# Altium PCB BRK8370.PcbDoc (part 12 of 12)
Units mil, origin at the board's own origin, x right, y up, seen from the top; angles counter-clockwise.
Board outline 8267.72 x 5708.66 mil, 6 copper layers (L1-TOP, L2-GND, L3-PWR, L4-PWR, L5-GND, L6-BOT), stack 68.606 mil thick; 319 components, 516 nets, 2008 pads, 1743 vias.
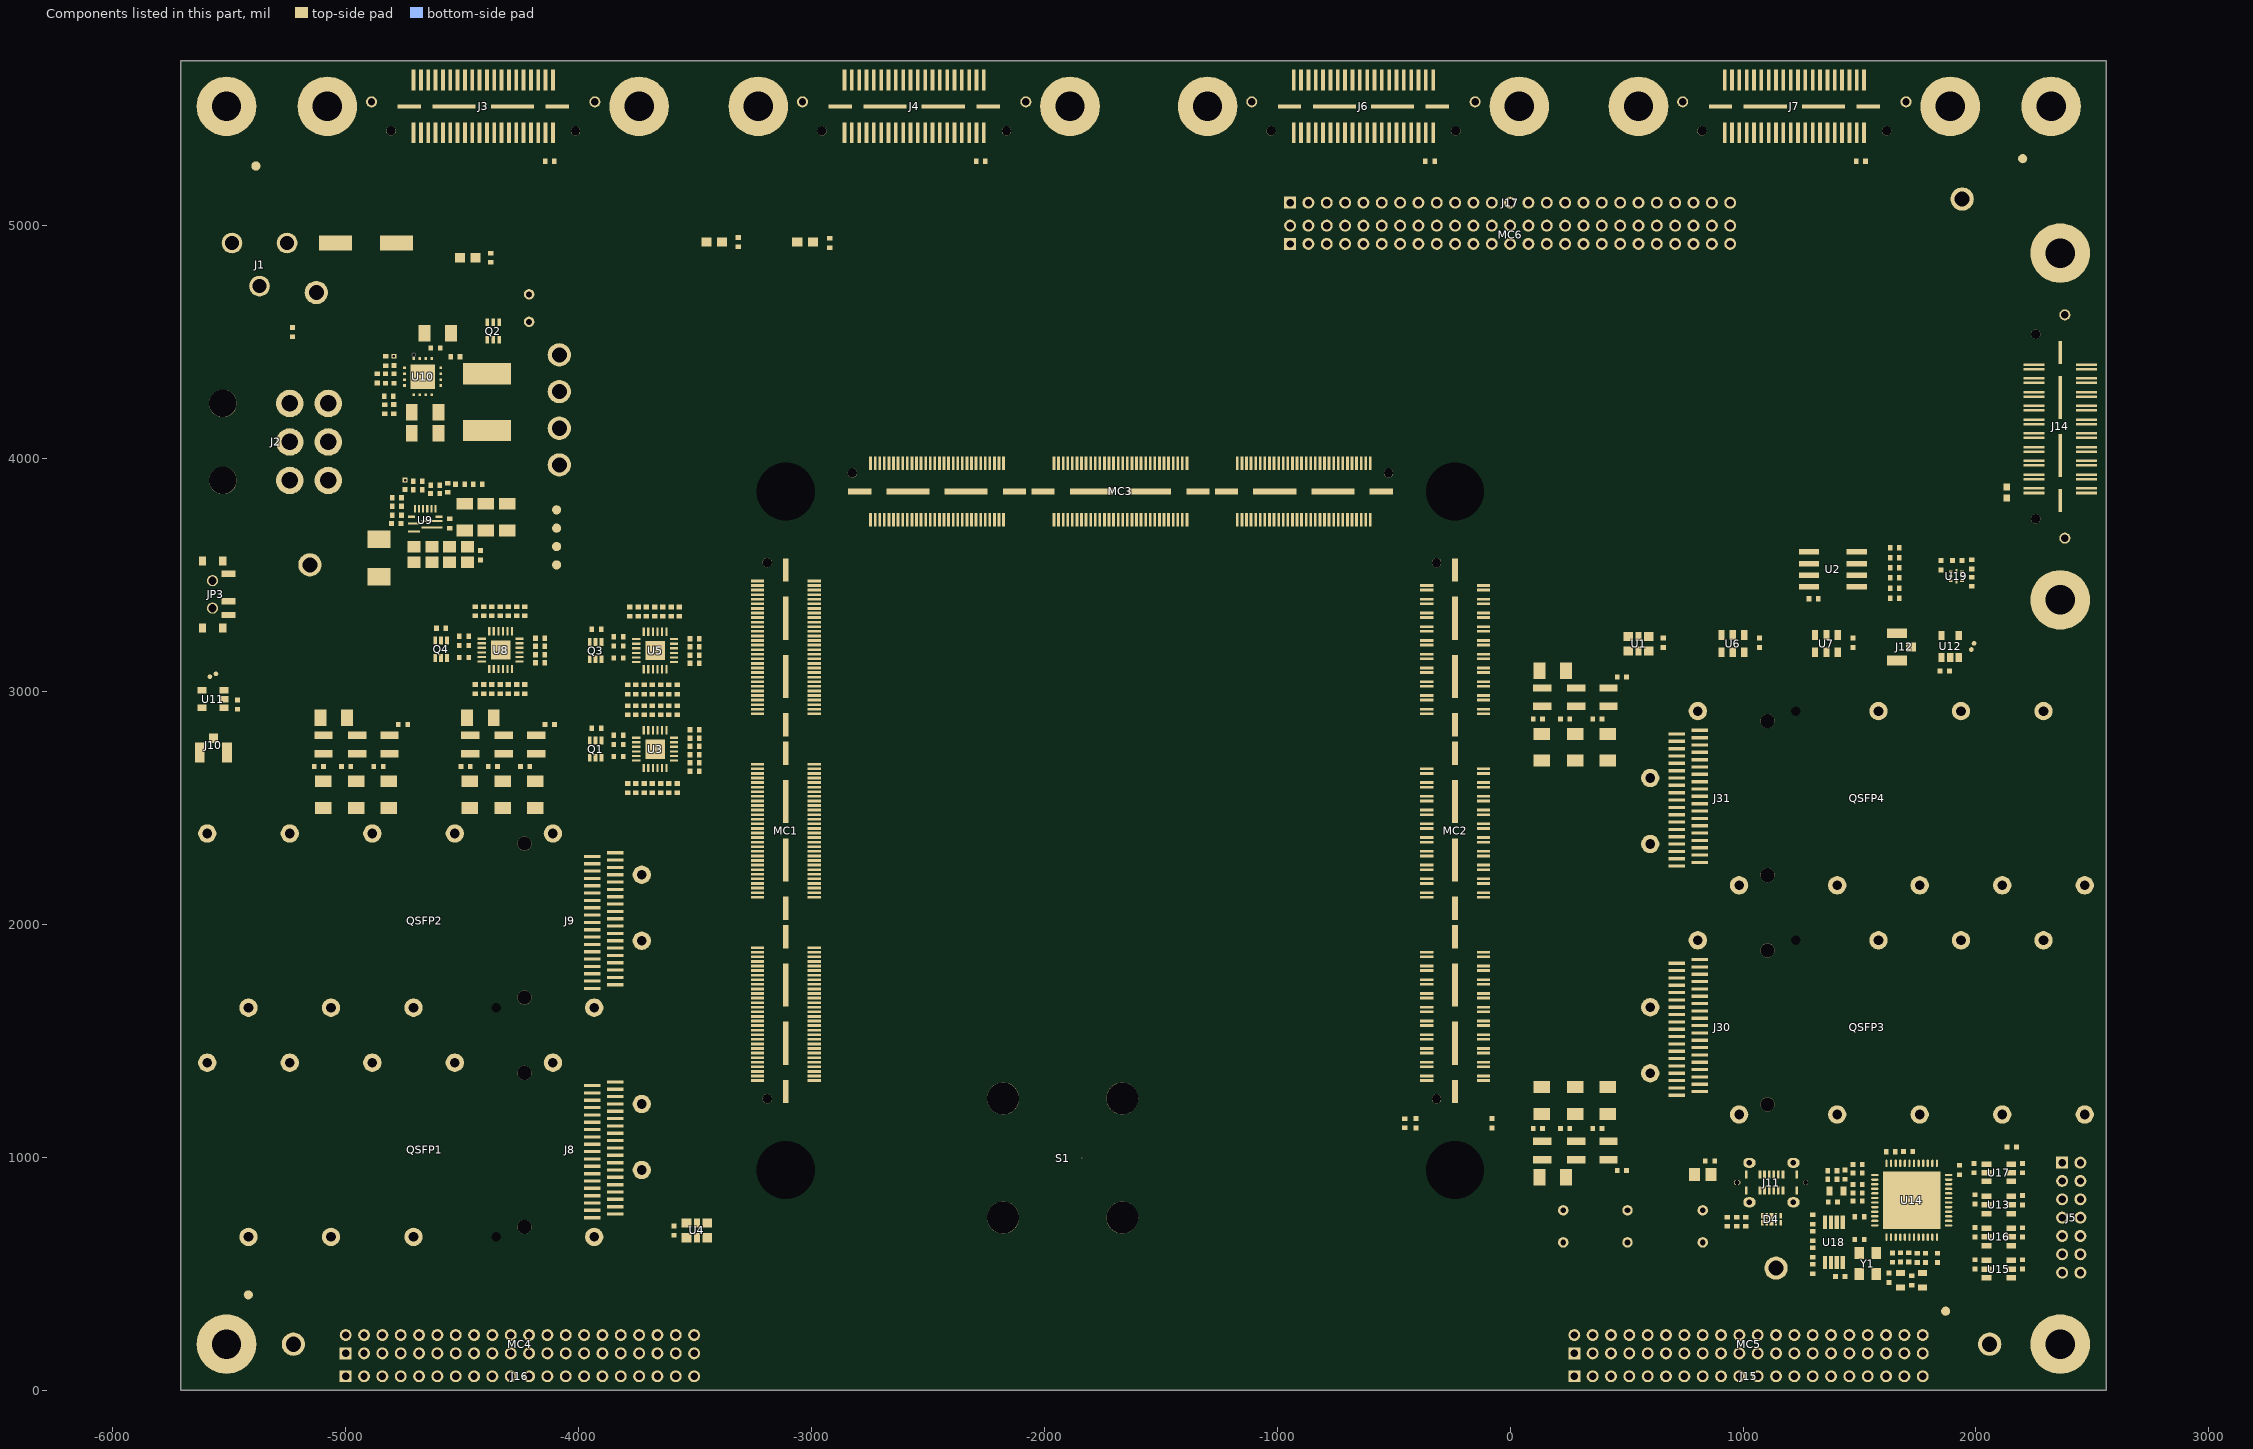
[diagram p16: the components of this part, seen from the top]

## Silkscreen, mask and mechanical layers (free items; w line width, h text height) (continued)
Fab Notes:
  drawing of 164 lines, arcs and shapes, not listed
  text "NOTES: /  / 1. MATERIAL: /    IT180A or equivalent /    Surface finish: ENIG /    Overall thickness: 93 mils +/-10% /  / 2. Fabricate to IPC-6012 (latest revision), Class 2 /  / 3. SOLDER RESIST: Glossy blue LPI applied over bare copper or gold/nickel plating /  / 4. SILKSCREEN: White /  / 5. All vendor markings must be on bottom side of PCB /  / 6. LOT CODE IDENTIFICATION: /    Supplier must add identifier and lot code date to silkscreen. /    LOT CODE DATE FORMAT: YYWW (YY = 2-digit year, WW = 2-digit week) /  / 7. Drill sizes are finished size after plating /  / 8. 100% electrical bare board test required for continuity /  / 9. IMPEDANCE CONTROL: /    See Layer Stackup Table on this drawing and refer to '.Part_Number'-PCBStackup.pdf /  / 10. PANELIZATION: /    1 pieces per array /    Tab routing required. Tab locations indicated by ::: (see Dimensions Gerber layer) /    OUTLINE DIMENSION TOLERANCE: +/-0.127 mm /    0.25-inch rails on all sides /  / 11. POFV: All 10-mil diameter vias must be filled using non-conductive epoxy and plated over. /  / 12. ROHS: Fabricate to meet EU RoHS directive. Supplier must add lead-free marking in silkscreen. /  / 13. UL: Supplier must add UL certification marking (94V-0) in silkscreen. /  / 14. Remove all non-functional pads from internal layers" at -12437.01,3732.28 h38
  text "LAYER STACKUP TABLE" at -12964.57,2842.52 h80
  text "S" at -10177.36,2762.75 h66.47
  text "i" at -10150.71,2762.75 h66.47
  text "n" at -10135.48,2762.75 h66.47
  text "g" at -10105.02,2762.74 h66.47
  text "l" at -10078.38,2762.75 h66.47
  text "e" at -10063.15,2762.75 h66.47
  text "-" at -10032.69,2762.76 h66.47
  text "E" at -10013.66,2762.75 h66.47
  text "n" at -9987.01,2762.75 h66.47
  text "d" at -9956.55,2762.75 h66.47
  text "e" at -9926.09,2762.75 h66.47
  text "d" at -9895.64,2762.75 h66.47
  text "D" at -9083,2762.75 h66.47
  text "i" at -9048.73,2762.75 h66.47
  text "f" at -9033.51,2762.75 h66.47
  text "f" at -9014.47,2762.75 h66.47
  text "e" at -8995.44,2762.75 h66.47
  text "r" at -8964.98,2762.75 h66.47
  text "e" at -8945.94,2762.75 h66.47
  text "n" at -8915.49,2762.75 h66.47
  text "t" at -8885.03,2762.75 h66.47
  text "i" at -8866,2762.75 h66.47
  text "a" at -8850.77,2762.75 h66.47
  text "l" at -8824.12,2762.75 h66.47
  text "D" at -8767.61,2762.75 h66.47
  text "i" at -8733.35,2762.75 h66.47
  text "f" at -8718.12,2762.75 h66.47
  text "f" at -8699.08,2762.75 h66.47
  text "e" at -8680.05,2762.75 h66.47
  text "r" at -8649.59,2762.75 h66.47
  text "e" at -8630.56,2762.75 h66.47
  text "n" at -8600.1,2762.75 h66.47
  text "t" at -8569.64,2762.75 h66.47
  text "i" at -8550.61,2762.75 h66.47
  text "a" at -8535.38,2762.75 h66.47
  text "l" at -8508.73,2762.75 h66.47
  text "D" at -8060.83,2762.75 h66.47
  text "i" at -8026.57,2762.75 h66.47
  text "f" at -8011.34,2762.75 h66.47
  text "f" at -7992.31,2762.75 h66.47
  text "e" at -7973.27,2762.75 h66.47
  text "r" at -7942.82,2762.75 h66.47
  text "e" at -7923.78,2762.75 h66.47
  text "n" at -7893.32,2762.75 h66.47
  text "t" at -7862.87,2762.75 h66.47
  text "i" at -7843.83,2762.75 h66.47
  text "a" at -7828.61,2762.75 h66.47
  text "l" at -7801.96,2762.75 h66.47
  text "D" at -7745.44,2762.75 h66.47
  text "i" at -7711.18,2762.75 h66.47
  text "f" at -7695.95,2762.75 h66.47
  text "f" at -7676.92,2762.75 h66.47
  text "e" at -7657.88,2762.75 h66.47
  text "r" at -7627.43,2762.75 h66.47
  text "e" at -7608.39,2762.75 h66.47
  text "n" at -7577.94,2762.75 h66.47
  text "t" at -7547.48,2762.75 h66.47
  text "i" at -7528.44,2762.75 h66.47
  text "a" at -7513.22,2762.75 h66.47
  text "l" at -7486.57,2762.75 h66.47
  text "M" at -10880.33,2689.29 h66.47
  text "a" at -10830.84,2689.29 h66.47
  text "t" at -10800.39,2689.29 h66.47
  text "e" at -10781.35,2689.29 h66.47
  text "r" at -10747.09,2689.29 h66.47
  text "i" at -10724.24,2689.29 h66.47
  text "a" at -10709.02,2689.29 h66.47
  text "l" at -10678.56,2689.29 h66.47
  text "T" at -10082.36,2686.61 h66.47
  text "r" at -10055.71,2686.61 h66.47
  text "a" at -10036.68,2686.61 h66.47
  text "c" at -10010.03,2686.61 h66.47
  text "e" at -9987.19,2686.61 h66.47
  text "S" at -9820.17,2686.61 h66.47
  text "i" at -9793.52,2686.61 h66.47
  text "n" at -9778.29,2686.61 h66.47
  text "g" at -9747.84,2686.6 h66.47
  text "l" at -9721.19,2686.61 h66.47
  text "e" at -9705.96,2686.61 h66.47
  text "-" at -9675.5,2686.62 h66.47
  text "E" at -9656.47,2686.61 h66.47
  text "n" at -9629.82,2686.61 h66.47
  text "d" at -9599.36,2686.61 h66.47
  text "e" at -9568.91,2686.61 h66.47
  text "d" at -9538.45,2686.61 h66.47
  text "T" at -9007,2686.61 h66.47
  text "r" at -8980.35,2686.61 h66.47
  text "a" at -8961.32,2686.61 h66.47
  text "c" at -8934.67,2686.61 h66.47
  text "e" at -8911.82,2686.61 h66.47
  text "T" at -8695.41,2686.61 h66.47
  text "r" at -8668.76,2686.61 h66.47
  text "a" at -8649.73,2686.61 h66.47
  text "c" at -8623.08,2686.61 h66.47
  text "e" at -8600.24,2686.61 h66.47
  text "T" at -7984.84,2686.61 h66.47
  text "r" at -7958.19,2686.61 h66.47
  text "a" at -7939.15,2686.61 h66.47
  text "c" at -7912.5,2686.61 h66.47
  text "e" at -7889.66,2686.61 h66.47
  text "T" at -7673.25,2686.61 h66.47
  text "r" at -7646.6,2686.61 h66.47
  text "a" at -7627.56,2686.61 h66.47
  text "c" at -7600.91,2686.61 h66.47
  text "e" at -7578.07,2686.61 h66.47
  text "G" at -12267.28,2613.15 h66.47
  text "e" at -12221.6,2613.15 h66.47
  text "r" at -12187.34,2613.15 h66.47
  text "b" at -12164.49,2613.15 h66.47
  text "e" at -12130.23,2613.15 h66.47
  text "r" at -12095.97,2613.15 h66.47
  text "M" at -11647.91,2613.15 h66.47
  text "a" at -11598.41,2613.15 h66.47
  text "t" at -11567.96,2613.15 h66.47
  text "e" at -11548.92,2613.15 h66.47
  text "r" at -11514.66,2613.15 h66.47
  text "i" at -11491.82,2613.15 h66.47
  text "a" at -11476.59,2613.15 h66.47
  text "l" at -11446.13,2613.15 h66.47
  text "M" at -11245.12,2613.15 h66.47
  text "a" at -11195.63,2613.15 h66.47
  text "t" at -11165.17,2613.15 h66.47
  text "e" at -11146.14,2613.15 h66.47
  text "r" at -11111.87,2613.15 h66.47
  text "i" at -11089.03,2613.15 h66.47
  text "a" at -11073.8,2613.15 h66.47
  text "l" at -11043.35,2613.15 h66.47
  text "E" at -11012.89,2613.15 h66.47
  text "r" at -10974.82,2613.15 h66.47
  text "T" at -10910.73,2613.15 h66.47
  text "h" at -10872.66,2613.15 h66.47
  text "i" at -10838.4,2613.15 h66.47
  text "c" at -10823.17,2613.15 h66.47
  text "k" at -10792.71,2613.15 h66.47
  text "n" at -10762.26,2613.15 h66.47
  text "e" at -10727.99,2613.15 h66.47
  text "s" at -10693.73,2613.15 h66.47
  text "s" at -10663.28,2613.15 h66.47
  text "C" at -10504.15,2610.47 h66.47
  text "o" at -10473.69,2610.47 h66.47
  text "p" at -10443.23,2610.46 h66.47
  text "p" at -10412.78,2610.46 h66.47
  text "e" at -10382.32,2610.47 h66.47
  text "r" at -10351.87,2610.47 h66.47
  text "I" at -10150.76,2610.47 h66.47
  text "m" at -10135.53,2610.47 h66.47
  text "p" at -10089.85,2610.46 h66.47
  text "e" at -10059.39,2610.47 h66.47
  text "d" at -10028.93,2610.47 h66.47
  text "a" at -9998.48,2610.47 h66.47
  text "n" at -9971.83,2610.47 h66.47
  text "c" at -9941.37,2610.47 h66.47
  text "e" at -9918.53,2610.47 h66.47
  text "T" at -9804.97,2610.47 h66.47
  text "r" at -9778.32,2610.47 h66.47
  text "a" at -9759.29,2610.47 h66.47
  text "c" at -9732.64,2610.47 h66.47
  text "e" at -9709.8,2610.47 h66.47
  text "W" at -9667.92,2610.47 h66.47
  text "i" at -9614.62,2610.47 h66.47
  text "d" at -9599.39,2610.47 h66.47
  text "t" at -9568.94,2610.47 h66.47
  text "h" at -9549.9,2610.47 h66.47
  text "I" at -9075.4,2610.47 h66.47
  text "m" at -9060.17,2610.47 h66.47
  text "p" at -9014.48,2610.46 h66.47
  text "e" at -8984.03,2610.47 h66.47
  text "d" at -8953.57,2610.47 h66.47
  text "a" at -8923.12,2610.47 h66.47
  text "n" at -8896.47,2610.47 h66.47
  text "c" at -8866.01,2610.47 h66.47
  text "e" at -8843.17,2610.47 h66.47
  text "W" at -8786.61,2610.47 h66.47
  text "i" at -8733.31,2610.47 h66.47
  text "d" at -8718.08,2610.47 h66.47
  text "t" at -8687.62,2610.47 h66.47
  text "h" at -8668.59,2610.47 h66.47
  text "/" at -8638.13,2610.46 h66.47
  text "S" at -8615.29,2610.47 h66.47
  text "p" at -8588.64,2610.46 h66.47
  text "a" at -8558.19,2610.47 h66.47
  text "c" at -8531.54,2610.47 h66.47
  text "e" at -8508.7,2610.47 h66.47
  text "I" at -8053.23,2610.47 h66.47
  text "m" at -8038.01,2610.47 h66.47
  text "p" at -7992.32,2610.46 h66.47
  text "e" at -7961.87,2610.47 h66.47
  text "d" at -7931.41,2610.47 h66.47
  text "a" at -7900.95,2610.47 h66.47
  text "n" at -7874.3,2610.47 h66.47
  text "c" at -7843.85,2610.47 h66.47
  text "e" at -7821.01,2610.47 h66.47
  text "W" at -7764.44,2610.47 h66.47
  text "i" at -7711.15,2610.47 h66.47
  text "d" at -7695.92,2610.47 h66.47
  text "t" at -7665.46,2610.47 h66.47
  text "h" at -7646.43,2610.47 h66.47
  text "/" at -7615.97,2610.46 h66.47
  text "S" at -7593.13,2610.47 h66.47
  text "p" at -7566.48,2610.46 h66.47
  text "a" at -7536.02,2610.47 h66.47
  text "c" at -7509.37,2610.47 h66.47
  text "e" at -7486.53,2610.47 h66.47
  text "L" at -12996.86,2537.01 h66.47
  text "a" at -12962.59,2537.01 h66.47
  text "y" at -12932.14,2537 h66.47
  text "e" at -12905.49,2537.01 h66.47
  text "r" at -12871.23,2537.01 h66.47
  text "L" at -12806.86,2537.01 h66.47
  text "a" at -12772.6,2537.01 h66.47
  text "y" at -12742.14,2537 h66.47
  text "e" at -12715.5,2537.01 h66.47
  text "r" at -12681.23,2537.01 h66.47
  text "N" at -12643.16,2537.01 h66.47
  text "a" at -12601.28,2537.01 h66.47
  text "m" at -12570.83,2537.01 h66.47
  text "e" at -12525.14,2537.01 h66.47
  text "L" at -12267.28,2537.01 h66.47
  text "a" at -12233.02,2537.01 h66.47
  text "y" at -12202.56,2537 h66.47
  text "e" at -12175.91,2537.01 h66.47
  text "r" at -12141.65,2537.01 h66.47
  text "M" at -12039.29,2537.01 h66.47
  text "a" at -11989.8,2537.01 h66.47
  text "t" at -11959.34,2537.01 h66.47
  text "e" at -11940.31,2537.01 h66.47
  text "r" at -11906.05,2537.01 h66.47
  text "i" at -11883.2,2537.01 h66.47
  text "a" at -11867.98,2537.01 h66.47
  text "l" at -11837.52,2537.01 h66.47
  text "T" at -11807.06,2537.01 h66.47
  text "y" at -11768.99,2537 h66.47
  text "p" at -11742.34,2537 h66.47
  text "e" at -11708.08,2537.01 h66.47
  text "C" at -11647.91,2537.01 h66.47
  text "o" at -11606.03,2537.01 h66.47
  text "n" at -11571.76,2537.01 h66.47
  text "s" at -11537.5,2537.01 h66.47
  text "t" at -11507.05,2537.01 h66.47
  text "r" at -11488.01,2537.01 h66.47
  text "u" at -11465.17,2537.01 h66.47
  text "c" at -11430.91,2537.01 h66.47
  text "t" at -11400.45,2537.01 h66.47
  text "i" at -11381.41,2537.01 h66.47
  text "o" at -11366.19,2537.01 h66.47
  text "n" at -11331.92,2537.01 h66.47
  text "(" at -11199.52,2537 h66.47
  text "1" at -11180.49,2537.01 h66.47
  text "G" at -11134.8,2537.01 h66.47
  text "H" at -11089.12,2537.01 h66.47
  text "z" at -11047.24,2537.01 h66.47
  text ")" at -11016.78,2537 h66.47
  text "(" at -10827.13,2537 h66.47
  text "m" at -10808.1,2537.01 h66.47
  text "i" at -10762.42,2537.01 h66.47
  text "l" at -10747.19,2537.01 h66.47
  text ")" at -10731.96,2537 h66.47
  text "W" at -10557.34,2534.33 h66.47
  text "e" at -10504.05,2534.33 h66.47
  text "i" at -10473.59,2534.33 h66.47
  text "g" at -10458.36,2534.32 h66.47
  text "h" at -10431.71,2534.33 h66.47
  text "t" at -10401.26,2534.33 h66.47
  text "(" at -10370.8,2534.32 h66.47
  text "o" at -10351.77,2534.33 h66.47
  text "z" at -10321.31,2534.33 h66.47
  text ")" at -10298.47,2534.32 h66.47
  text "(" at -10105.16,2534.32 h66.47
  text "o" at -10086.13,2534.33 h66.47
  text "h" at -10055.67,2534.33 h66.47
  text "m" at -10025.21,2534.33 h66.47
  text "s" at -9979.53,2534.33 h66.47
  text ")" at -9956.69,2534.32 h66.47
  text "(" at -9732.77,2534.32 h66.47
  text "m" at -9713.74,2534.33 h66.47
  text "i" at -9668.05,2534.33 h66.47
  text "l" at -9652.83,2534.33 h66.47
  text "s" at -9637.6,2534.33 h66.47
  text ")" at -9614.76,2534.32 h66.47
  text "R" at -9432.58,2534.33 h66.47
  text "e" at -9402.13,2534.33 h66.47
  text "f" at -9371.67,2534.33 h66.47
  text "e" at -9352.64,2534.33 h66.47
  text "r" at -9322.18,2534.33 h66.47
  text "e" at -9303.15,2534.33 h66.47
  text "n" at -9272.69,2534.33 h66.47
  text "c" at -9242.23,2534.33 h66.47
  text "e" at -9219.39,2534.33 h66.47
  text "(" at -9029.8,2534.32 h66.47
  text "o" at -9010.76,2534.33 h66.47
  text "h" at -8980.31,2534.33 h66.47
  text "m" at -8949.85,2534.33 h66.47
  text "s" at -8904.17,2534.33 h66.47
  text ")" at -8881.33,2534.32 h66.47
  text "(" at -8699.21,2534.32 h66.47
  text "m" at -8680.18,2534.33 h66.47
  text "i" at -8634.49,2534.33 h66.47
  text "l" at -8619.26,2534.33 h66.47
  text "s" at -8604.04,2534.33 h66.47
  text ")" at -8581.19,2534.32 h66.47
  text "R" at -8410.42,2534.33 h66.47
  text "e" at -8379.96,2534.33 h66.47
  text "f" at -8349.51,2534.33 h66.47
  text "e" at -8330.47,2534.33 h66.47
  text "r" at -8300.02,2534.33 h66.47
  text "e" at -8280.98,2534.33 h66.47
  text "n" at -8250.53,2534.33 h66.47
  text "c" at -8220.07,2534.33 h66.47
  text "e" at -8197.23,2534.33 h66.47
  text "(" at -8007.64,2534.32 h66.47
  text "o" at -7988.6,2534.33 h66.47
  text "h" at -7958.14,2534.33 h66.47
  text "m" at -7927.69,2534.33 h66.47
  text "s" at -7882,2534.33 h66.47
  text ")" at -7859.16,2534.32 h66.47
  text "(" at -7677.05,2534.32 h66.47
  text "m" at -7658.01,2534.33 h66.47
  text "i" at -7612.33,2534.33 h66.47
  text "l" at -7597.1,2534.33 h66.47
  text "s" at -7581.87,2534.33 h66.47
  text ")" at -7559.03,2534.32 h66.47
  text "R" at -7388.26,2534.33 h66.47
  text "e" at -7357.8,2534.33 h66.47
  text "f" at -7327.35,2534.33 h66.47
  text "e" at -7308.31,2534.33 h66.47
  text "r" at -7277.85,2534.33 h66.47
  text "e" at -7258.82,2534.33 h66.47
  text "n" at -7228.36,2534.33 h66.47
  text "c" at -7197.91,2534.33 h66.47
  text "e" at -7175.06,2534.33 h66.47
  text "O" at -12806.86,2426.61 h62.78
  text "v" at -12761.18,2426.61 h62.78
  text "e" at -12734.53,2426.61 h62.78
  text "r" at -12704.07,2426.61 h62.78
  text "l" at -12685.04,2426.61 h62.78
  text "a" at -12673.62,2426.61 h62.78
  text "y" at -12643.16,2426.59 h62.78
  text "T" at -12601.28,2426.61 h62.78
  text "o" at -12567.02,2426.61 h62.78
  text "p" at -12536.57,2426.59 h62.78
  text "G" at -12267.28,2426.61 h62.78
  text "T" at -12225.41,2426.61 h62.78
  text "O" at -12191.14,2426.61 h62.78
  text "S" at -12039.29,2426.61 h62.78
  text "i" at -12001.22,2426.61 h62.78
  text "l" at -11989.8,2426.61 h62.78
  text "k" at -11978.38,2426.61 h62.78
  text "s" at -11951.73,2426.61 h62.78
  text "c" at -11921.27,2426.61 h62.78
  text "r" at -11890.82,2426.61 h62.78
  text "e" at -11871.78,2426.61 h62.78
  text "e" at -11841.33,2426.61 h62.78
  text "n" at -11810.87,2426.61 h62.78
  text "S" at -12806.86,2350.47 h62.78
  text "o" at -12768.79,2350.47 h62.78
  text "l" at -12738.34,2350.47 h62.78
  text "d" at -12726.92,2350.47 h62.78
  text "e" at -12696.46,2350.47 h62.78
  text "r" at -12666,2350.47 h62.78
  text "M" at -12631.74,2350.47 h62.78
  text "a" at -12589.86,2350.47 h62.78
  text "s" at -12559.41,2350.47 h62.78
  text "k" at -12528.95,2350.47 h62.78
  text "T" at -12487.07,2350.47 h62.78
  text "o" at -12452.81,2350.47 h62.78
  text "p" at -12422.35,2350.45 h62.78
  text "G" at -12267.28,2350.47 h62.78
  text "T" at -12225.41,2350.47 h62.78
  text "S" at -12191.14,2350.47 h62.78
  text "S" at -12039.29,2350.47 h62.78
  text "o" at -12001.22,2350.47 h62.78
  text "l" at -11970.77,2350.47 h62.78
  text "d" at -11959.34,2350.47 h62.78
  text "e" at -11928.89,2350.47 h62.78
  text "r" at -11898.43,2350.47 h62.78
  text "R" at -11864.17,2350.47 h62.78
  text "e" at -11822.29,2350.47 h62.78
  text "s" at -11791.84,2350.47 h62.78
  text "i" at -11761.38,2350.47 h62.78
  text "s" at -11749.96,2350.47 h62.78
  text "t" at -11719.5,2350.47 h62.78
  text "3" at -11131.12,2347.78 h66.47
  text "." at -11104.47,2347.78 h66.47
  text "5" at -11089.25,2347.78 h66.47
  text "1" at -12996.86,2274.33 h62.78
  text "L" at -12806.86,2274.33 h62.78
  text "1" at -12776.41,2274.33 h62.78
  text "-" at -12745.95,2274.35 h62.78
  text "T" at -12726.92,2274.33 h62.78
  text "O" at -12692.65,2274.33 h62.78
  text "P" at -12646.97,2274.33 h62.78
  text "G" at -12267.28,2274.33 h62.78
  text "T" at -12225.41,2274.33 h62.78
  text "L" at -12191.14,2274.33 h62.78
  text "C" at -12039.29,2274.33 h62.78
  text "o" at -11997.41,2274.33 h62.78
  text "p" at -11966.96,2274.31 h62.78
  text "p" at -11936.5,2274.31 h62.78
  text "e" at -11906.05,2274.33 h62.78
  text "r" at -11875.59,2274.33 h62.78
  text "0" at -10804.34,2271.64 h66.47
  text "." at -10777.69,2271.64 h66.47
  text "7" at -10762.46,2271.64 h66.47
  text "1" at -10561.14,2271.64 h66.47
  text "/" at -10534.5,2271.64 h66.47
  text "2" at -10511.65,2271.64 h66.47
  text "+" at -10473.58,2271.65 h66.47
  text "p" at -10435.51,2271.64 h66.47
  text "l" at -10405.06,2271.64 h66.47
  text "a" at -10389.83,2271.64 h66.47
  text "t" at -10363.18,2271.64 h66.47
  text "i" at -10344.14,2271.64 h66.47
  text "n" at -10328.92,2271.64 h66.47
  text "g" at -10298.46,2271.64 h66.47
  text "5" at -10044.36,2271.64 h66.47
  text "0" at -10017.71,2271.64 h66.47
  text "4" at -9725.17,2271.64 h66.47
  text "." at -9698.53,2271.64 h66.47
  text "9" at -9683.3,2271.64 h66.47
  text "6" at -9656.65,2271.64 h66.47
  text "3" at -9630,2271.64 h66.47
  text "L" at -9333.79,2271.64 h66.47
  text "2" at -9310.95,2271.64 h66.47
  text "1" at -8984.2,2271.64 h66.47
  text "0" at -8957.55,2271.64 h66.47
  text "0" at -8930.9,2271.64 h66.47
  text "3" at -8722.01,2271.64 h66.47
  text "." at -8695.36,2271.64 h66.47
  text "3" at -8680.13,2271.64 h66.47
  text "/" at -8642.06,2271.64 h66.47
  text "5" at -8607.8,2271.64 h66.47
  text "." at -8581.15,2271.64 h66.47
  text "7" at -8565.92,2271.64 h66.47
  text "L" at -8311.62,2271.64 h66.47
  text "2" at -8288.78,2271.64 h66.47
  text "9" at -7950.64,2271.64 h66.47
  text "0" at -7923.99,2271.64 h66.47
  text "4" at -7699.85,2271.64 h66.47
  text "." at -7673.2,2271.64 h66.47
  text "0" at -7657.97,2271.64 h66.47
  text "/" at -7619.9,2271.64 h66.47
  text "6" at -7585.64,2271.64 h66.47
  text "." at -7558.99,2271.64 h66.47
  text "0" at -7543.76,2271.64 h66.47
  text "L" at -7289.46,2271.64 h66.47
  text "2" at -7266.62,2271.64 h66.47
  text "P" at -12039.29,2198.19 h62.78
  text "r" at -12001.22,2198.19 h62.78
  text "e" at -11982.19,2198.19 h62.78
  text "p" at -11951.73,2198.17 h62.78
  text "r" at -11921.27,2198.19 h62.78
  text "e" at -11902.24,2198.19 h62.78
  text "g" at -11871.78,2198.17 h62.78
  text "1" at -11647.91,2195.5 h66.47
  text "0" at -11621.26,2195.5 h66.47
  text "8" at -11594.61,2195.5 h66.47
  text "0" at -11567.96,2195.5 h66.47
  text "R" at -11529.89,2195.5 h66.47
  text "C" at -11499.43,2195.5 h66.47
  text "6" at -11468.98,2195.5 h66.47
  text "8" at -11442.33,2195.5 h66.47
  text "3" at -11142.52,2195.5 h66.47
  text "." at -11115.87,2195.5 h66.47
  text "6" at -11100.65,2195.5 h66.47
  text "9" at -11074,2195.5 h66.47
  text "2" at -10815.74,2195.5 h66.47
  text "." at -10789.09,2195.5 h66.47
  text "9" at -10773.86,2195.5 h66.47
  text "7" at -10747.21,2195.5 h66.47
  text "2" at -12996.86,2122.05 h62.78
  text "L" at -12806.86,2122.05 h62.78
  text "2" at -12776.41,2122.05 h62.78
  text "-" at -12745.95,2122.07 h62.78
  text "G" at -12726.92,2122.05 h62.78
  text "N" at -12685.04,2122.05 h62.78
  text "D" at -12646.97,2122.05 h62.78
  text "G" at -12267.28,2122.05 h62.78
  text "1" at -12225.41,2122.05 h62.78
  text "C" at -12039.29,2122.05 h62.78
  text "o" at -11997.41,2122.05 h62.78
  text "p" at -11966.96,2122.03 h62.78
  text "p" at -11936.5,2122.03 h62.78
  text "e" at -11906.05,2122.05 h62.78
  text "r" at -11875.59,2122.05 h62.78
  text "0" at -10804.34,2119.36 h66.47
  text "." at -10777.69,2119.36 h66.47
  text "7" at -10762.46,2119.36 h66.47
  text "1" at -10454.75,2119.36 h66.47
  text "/" at -10428.1,2119.36 h66.47
  text "2" at -10405.26,2119.36 h66.47
  text "C" at -12039.29,2045.91 h62.78
  text "o" at -11997.41,2045.91 h62.78
  text "r" at -11966.96,2045.91 h62.78
  text "e" at -11947.92,2045.91 h62.78
  text "2" at -11647.91,2043.22 h66.47
  text "*" at -11621.26,2043.24 h66.47
  text "7" at -11594.61,2043.22 h66.47
  text "6" at -11567.96,2043.22 h66.47
  text "2" at -11541.31,2043.22 h66.47
  text "8" at -11514.66,2043.22 h66.47
  text "4" at -11142.52,2043.22 h66.47
  text "." at -11115.87,2043.22 h66.47
  text "2" at -11100.65,2043.22 h66.47
  text "4" at -11074,2043.22 h66.47
  text "1" at -10830.93,2043.22 h66.47
  text "6" at -10804.29,2043.22 h66.47
  text "." at -10777.64,2043.22 h66.47
  text "1" at -10762.41,2043.22 h66.47
  text "4" at -10735.76,2043.22 h66.47
  text "-" at -12745.95,1969.79 h62.78
  text "3" at -12996.86,1969.76 h62.78
  text "L" at -12806.86,1969.77 h62.78
  text "3" at -12776.41,1969.76 h62.78
  text "P" at -12726.92,1969.77 h62.78
  text "W" at -12688.85,1969.77 h62.78
  text "R" at -12631.74,1969.77 h62.78
  text "G" at -12267.28,1969.77 h62.78
  text "4" at -12225.41,1969.77 h62.78
  text "C" at -12039.29,1969.77 h62.78
  text "o" at -11997.41,1969.77 h62.78
  text "p" at -11966.96,1969.75 h62.78
  text "p" at -11936.5,1969.75 h62.78
  text "e" at -11906.05,1969.77 h62.78
  text "r" at -11875.59,1969.77 h62.78
  text "0" at -10804.34,1967.08 h66.47
  text "." at -10777.69,1967.08 h66.47
  text "7" at -10762.46,1967.08 h66.47
  text "1" at -10454.75,1967.08 h66.47
  text "/" at -10428.1,1967.08 h66.47
  text "2" at -10405.26,1967.08 h66.47
  text "P" at -12039.29,1893.63 h62.78
  text "r" at -12001.22,1893.63 h62.78
  text "e" at -11982.19,1893.62 h62.78
  text "p" at -11951.73,1893.61 h62.78
  text "r" at -11921.27,1893.63 h62.78
  text "e" at -11902.24,1893.62 h62.78
  text "g" at -11871.78,1893.6 h62.78
  text "5" at -11647.91,1890.94 h66.47
  text "*" at -11621.26,1890.96 h66.47
  text "7" at -11594.61,1890.94 h66.47
  text "6" at -11567.96,1890.94 h66.47
  text "2" at -11541.31,1890.94 h66.47
  text "8" at -11514.66,1890.94 h66.47
  text "4" at -11142.52,1890.94 h66.47
  text "." at -11115.87,1890.94 h66.47
  text "3" at -11100.65,1890.94 h66.47
  text "2" at -11074,1890.94 h66.47
  text "-" at -10777.74,1890.95 h66.47
  text "4" at -12996.86,1817.49 h62.78
  text "L" at -12806.86,1817.49 h62.78
  text "4" at -12776.41,1817.49 h62.78
  text "-" at -12745.95,1817.51 h62.78
  text "P" at -12726.92,1817.49 h62.78
  text "W" at -12688.85,1817.49 h62.78
  text "R" at -12631.74,1817.49 h62.78
  text "G" at -12267.28,1817.48 h62.78
  text "5" at -12225.41,1817.48 h62.78
  text "C" at -12039.29,1817.48 h62.78
  text "o" at -11997.41,1817.48 h62.78
  text "p" at -11966.96,1817.47 h62.78
  text "p" at -11936.5,1817.47 h62.78
  text "e" at -11906.05,1817.48 h62.78
  text "r" at -11875.59,1817.49 h62.78
  text "0" at -10804.34,1814.8 h66.47
  text "." at -10777.69,1814.8 h66.47
  text "7" at -10762.46,1814.8 h66.47
  text "1" at -10454.75,1814.8 h66.47
  text "/" at -10428.1,1814.79 h66.47
  text "2" at -10405.26,1814.8 h66.47
  text "C" at -12039.29,1741.34 h62.78
  text "o" at -11997.41,1741.34 h62.78
  text "r" at -11966.96,1741.35 h62.78
  text "e" at -11947.92,1741.34 h62.78
  text "2" at -11647.91,1738.66 h66.47
  text "*" at -11621.26,1738.68 h66.47
  text "7" at -11594.61,1738.66 h66.47
  text "6" at -11567.96,1738.66 h66.47
  text "2" at -11541.31,1738.66 h66.47
  text "8" at -11514.66,1738.66 h66.47
  text "4" at -11142.52,1738.66 h66.47
  text "." at -11115.87,1738.66 h66.47
  text "2" at -11100.65,1738.66 h66.47
  text "4" at -11074,1738.66 h66.47
  text "1" at -10830.93,1738.66 h66.47
  text "6" at -10804.29,1738.66 h66.47
  text "." at -10777.64,1738.66 h66.47
  text "1" at -10762.41,1738.66 h66.47
  text "4" at -10735.76,1738.66 h66.47
  text "5" at -12996.86,1665.2 h62.78
  text "L" at -12806.86,1665.2 h62.78
  text "5" at -12776.41,1665.2 h62.78
  text "-" at -12745.95,1665.23 h62.78
  text "G" at -12726.92,1665.2 h62.78
  text "N" at -12685.04,1665.2 h62.78
  text "D" at -12646.97,1665.2 h62.78
  text "G" at -12267.28,1665.2 h62.78
  text "6" at -12225.41,1665.2 h62.78
  text "C" at -12039.29,1665.2 h62.78
  text "o" at -11997.41,1665.2 h62.78
  text "p" at -11966.96,1665.18 h62.78
  text "p" at -11936.5,1665.18 h62.78
  text "e" at -11906.05,1665.2 h62.78
  text "r" at -11875.59,1665.2 h62.78
  text "0" at -10804.34,1662.52 h66.47
  text "." at -10777.69,1662.52 h66.47
  text "7" at -10762.46,1662.52 h66.47
  text "1" at -10454.75,1662.52 h66.47
  text "/" at -10428.1,1662.51 h66.47
  text "2" at -10405.26,1662.52 h66.47
  text "P" at -12039.29,1589.06 h62.78
  text "r" at -12001.22,1589.06 h62.78
  text "e" at -11982.19,1589.06 h62.78
  text "p" at -11951.73,1589.04 h62.78
  text "r" at -11921.27,1589.06 h62.78
  text "e" at -11902.24,1589.06 h62.78
  text "g" at -11871.78,1589.04 h62.78
  text "1" at -11647.91,1586.38 h66.47
  text "0" at -11621.26,1586.38 h66.47
  text "8" at -11594.61,1586.38 h66.47
  text "0" at -11567.96,1586.38 h66.47
  text "R" at -11529.89,1586.38 h66.47
  text "C" at -11499.43,1586.38 h66.47
  text "6" at -11468.98,1586.38 h66.47
  text "8" at -11442.33,1586.38 h66.47
  text "3" at -11142.52,1586.38 h66.47
  text "." at -11115.87,1586.38 h66.47
  text "6" at -11100.65,1586.38 h66.47
  text "9" at -11074,1586.38 h66.47
  text "2" at -10815.74,1586.38 h66.47
  text "." at -10789.09,1586.38 h66.47
  text "9" at -10773.86,1586.38 h66.47
  text "7" at -10747.21,1586.38 h66.47
  text "6" at -12996.86,1512.92 h62.78
  text "L" at -12806.86,1512.92 h62.78
  text "6" at -12776.41,1512.92 h62.78
  text "-" at -12745.95,1512.95 h62.78
  text "B" at -12726.92,1512.92 h62.78
  text "O" at -12688.85,1512.92 h62.78
  text "T" at -12643.16,1512.92 h62.78
  text "G" at -12267.28,1512.92 h62.78
  text "B" at -12225.41,1512.92 h62.78
  text "L" at -12187.34,1512.92 h62.78
  text "C" at -12039.29,1512.92 h62.78
  text "o" at -11997.41,1512.92 h62.78
  text "p" at -11966.96,1512.9 h62.78
  text "p" at -11936.5,1512.9 h62.78
  text "e" at -11906.05,1512.92 h62.78
  text "r" at -11875.59,1512.92 h62.78
  text "0" at -10804.34,1510.24 h66.47
  text "." at -10777.69,1510.24 h66.47
  text "7" at -10762.46,1510.24 h66.47
  text "1" at -10561.14,1510.24 h66.47
  text "/" at -10534.5,1510.23 h66.47
  text "2" at -10511.65,1510.24 h66.47
  text "+" at -10473.58,1510.24 h66.47
  text "p" at -10435.51,1510.23 h66.47
  text "l" at -10405.06,1510.24 h66.47
  text "a" at -10389.83,1510.24 h66.47
  text "t" at -10363.18,1510.24 h66.47
  text "i" at -10344.14,1510.24 h66.47
  text "n" at -10328.92,1510.24 h66.47
  text "g" at -10298.46,1510.23 h66.47
  text "5" at -10044.36,1510.24 h66.47
  text "0" at -10017.71,1510.24 h66.47
  text "4" at -9725.17,1510.24 h66.47
  text "." at -9698.53,1510.24 h66.47
  text "9" at -9683.3,1510.24 h66.47
  text "6" at -9656.65,1510.24 h66.47
  text "3" at -9630,1510.24 h66.47
  text "L" at -9333.79,1510.24 h66.47
  text "5" at -9310.95,1510.24 h66.47
  text "1" at -8984.2,1510.24 h66.47
  text "0" at -8957.55,1510.24 h66.47
  text "0" at -8930.9,1510.24 h66.47
  text "3" at -8714.41,1510.24 h66.47
  text "." at -8687.76,1510.24 h66.47
  text "3" at -8672.53,1510.24 h66.47
  text "/" at -8634.46,1510.23 h66.47
  text "5" at -8611.62,1510.24 h66.47
  text "." at -8584.97,1510.24 h66.47
  text "7" at -8569.74,1510.24 h66.47
  text "L" at -8311.62,1510.24 h66.47
  text "5" at -8288.78,1510.24 h66.47
  text "9" at -7950.64,1510.24 h66.47
  text "0" at -7923.99,1510.24 h66.47
  text "4" at -7699.85,1510.24 h66.47
  text "." at -7673.2,1510.24 h66.47
  text "0" at -7657.97,1510.24 h66.47
  text "/" at -7619.9,1510.23 h66.47
  text "6" at -7585.64,1510.24 h66.47
  text "." at -7558.99,1510.24 h66.47
  text "0" at -7543.76,1510.24 h66.47
  text "L" at -7289.46,1510.24 h66.47
  text "5" at -7266.62,1510.24 h66.47
  text "S" at -12806.86,1436.78 h62.78
  text "o" at -12768.79,1436.78 h62.78
  text "l" at -12738.34,1436.78 h62.78
  text "d" at -12726.92,1436.78 h62.78
  text "e" at -12696.46,1436.78 h62.78
  text "r" at -12666,1436.78 h62.78
  text "M" at -12631.74,1436.78 h62.78
  text "a" at -12589.86,1436.78 h62.78
  text "s" at -12559.41,1436.78 h62.78
  text "k" at -12528.95,1436.78 h62.78
  text "B" at -12487.07,1436.78 h62.78
  text "o" at -12449,1436.78 h62.78
  text "t" at -12418.55,1436.78 h62.78
  text "t" at -12403.32,1436.78 h62.78
  text "o" at -12388.09,1436.78 h62.78
  text "m" at -12357.64,1436.78 h62.78
  text "G" at -12267.28,1436.78 h62.78
  text "B" at -12225.41,1436.78 h62.78
  text "S" at -12187.34,1436.78 h62.78
  text "S" at -12039.29,1436.78 h62.78
  text "o" at -12001.22,1436.78 h62.78
  text "l" at -11970.77,1436.78 h62.78
  text "d" at -11959.34,1436.78 h62.78
  text "e" at -11928.89,1436.78 h62.78
  text "r" at -11898.43,1436.78 h62.78
  text "R" at -11864.17,1436.78 h62.78
  text "e" at -11822.29,1436.78 h62.78
  text "s" at -11791.84,1436.78 h62.78
  text "i" at -11761.38,1436.78 h62.78
  text "s" at -11749.96,1436.78 h62.78
  text "t" at -11719.5,1436.78 h62.78
  text "3" at -11131.12,1434.1 h66.47
  text "." at -11104.47,1434.1 h66.47
  text "5" at -11089.25,1434.1 h66.47
  text "O" at -12806.86,1360.64 h62.78
  text "v" at -12761.18,1360.64 h62.78
  text "e" at -12734.53,1360.64 h62.78
  text "r" at -12704.07,1360.64 h62.78
  text "l" at -12685.04,1360.64 h62.78
  text "a" at -12673.62,1360.64 h62.78
  text "y" at -12643.16,1360.62 h62.78
  text "B" at -12601.28,1360.64 h62.78
  text "o" at -12563.21,1360.64 h62.78
  text "t" at -12532.76,1360.64 h62.78
  text "t" at -12517.53,1360.64 h62.78
  text "o" at -12502.3,1360.64 h62.78
  text "m" at -12471.85,1360.64 h62.78
  text "G" at -12267.28,1360.64 h62.78
  text "B" at -12225.41,1360.64 h62.78
  text "O" at -12187.34,1360.64 h62.78
  text "S" at -12039.29,1360.64 h62.78
  text "i" at -12001.22,1360.64 h62.78
  text "l" at -11989.8,1360.64 h62.78
  text "k" at -11978.38,1360.64 h62.78
  text "s" at -11951.73,1360.64 h62.78
  text "c" at -11921.27,1360.64 h62.78
  text "r" at -11890.82,1360.64 h62.78
  text "e" at -11871.78,1360.64 h62.78
  text "e" at -11841.33,1360.64 h62.78
  text "n" at -11810.87,1360.64 h62.78
Assy Notes Top:
  text "NOTES /  / 1. JSO1-JSO4 ARE PRESS-FIT ATTACHED TO THE PCB. THE MATING JSO HARDWARE MUST BE ATTACHED TO THE PRESS-FIT PIECE AFTER ASSEMBLY. /  / 1. SOLDER QSFP CAGES QSFP1, QSFP2, QSFP3 AND QSFP4 IN FOUR PLACES EACH ON BOTTOM SIDE AS INDICATED." at -6466.99,6421.19 h50
Assy Notes Bot:
  circle w10: c-3934.68,655.87 r74.01
  circle w10: c-5418.94,655.87 r74.01
  circle w10: c-5596.1,1403.91 r74.01
  circle w10: c-4111.85,1403.91 r74.01
  circle w10: c-3934.68,1640.13 r74.01
  circle w10: c-5418.94,1640.13 r74.01
  circle w10: c-5596.1,2388.16 r74.01
  circle w10: c-4111.85,2388.16 r74.01
  circle w10: c984.68,1184.68 r74.01
  circle w10: c2468.94,1184.68 r74.01
  circle w10: c2291.77,1932.71 r74.01
  circle w10: c807.52,1932.71 r74.01
  circle w10: c984.68,2168.93 r74.01
  circle w10: c2468.94,2168.93 r74.01
  circle w10: c2291.77,2916.96 r74.01
  circle w10: c807.52,2916.96 r74.01
  lines w10: 2341.5,2976.11 2426.5,3061.11 2706.69,3061.11
  text "SOLDER ON BOTTOM SIDE / (4 PLACES EACH QSFP)" at 3779.99,2802.73 h60
Drill Drawing:
  drawing of 161 lines, arcs and shapes, not listed
  text "DRILL TABLE" at -12598.43,854.33 h60
  text "Symbol" at -12562.88,739.91 h54
  text "Count" at -12181.87,739.91 h54
  text "Finished Hole Size" at -11686.01,739.91 h54
  text "Plated" at -10675.2,739.91 h54
  text "Drill Layer Pair" at -10294.2,739.91 h54
  text "Via/Pad" at -9400.36,739.91 h54
  text "Hole Tolerance" at -8956.37,739.91 h54
  text "Comment" at -8143.5,739.91 h54
  text "1746" at -12181.87,627.41 h45
  text "10.00mil (0.254mm)" at -11686.01,627.41 h45
  text "PTH" at -10675.2,627.41 h45
  text "L1-TOP - L6-BOT" at -10294.2,627.41 h45
  text "(Mixed)" at -9400.36,627.41 h45
  text "+/-3.00mil" at -8956.37,627.41 h45
  text "1" at -12181.87,514.91 h45
  text "20.47mil (0.520mm)" at -11686.01,514.91 h45
  text "NPTH" at -10675.2,514.91 h45
  text "L1-TOP - L6-BOT" at -10294.2,514.91 h45
  text "Pad" at -9400.36,514.91 h45
  text "+/-3.00mil" at -8956.37,514.91 h45
  text "D" at -12585.04,506.92 h50
  text "1" at -12181.87,402.41 h45
  text "20.47mil (0.520mm)" at -11686.01,402.41 h45
  text "NPTH" at -10675.2,402.41 h45
  text "L1-TOP - L6-BOT" at -10294.2,402.41 h45
  text "Pad" at -9400.36,402.41 h45
  text "+/-3.00mil" at -8956.37,402.41 h45
  text "B" at -12585.04,394.42 h50
  text "4" at -12181.87,289.91 h45
  text "23.62mil (0.600mm)" at -11686.01,289.91 h45
  text "PTH" at -10675.2,289.91 h45
  text "L1-TOP - L6-BOT" at -10294.2,289.91 h45
  text "Pad" at -9400.36,289.91 h45
  text "+/-3.00mil" at -8956.37,289.91 h45
  text "C" at -12585.04,281.92 h50
  text "8" at -12181.87,177.41 h45
  text "25.00mil (0.635mm)" at -11686.01,177.41 h45
  text "PTH" at -10675.2,177.41 h45
  text "L1-TOP - L6-BOT" at -10294.2,177.41 h45
  text "Pad" at -9400.36,177.41 h45
  text "+/-3.00mil" at -8956.37,177.41 h45
  text "209" at -12181.87,64.91 h45
  text "31.50mil (0.800mm)" at -11686.01,64.91 h45
  text "PTH" at -10675.2,64.91 h45
  text "L1-TOP - L6-BOT" at -10294.2,64.91 h45
  text "Pad" at -9400.36,64.91 h45
  text "+/-3.15mil" at -8956.37,64.91 h45
  text "10" at -12181.87,-47.59 h45
  text "31.50mil (0.800mm)" at -11686.01,-47.59 h45
  text "PTH" at -10675.2,-47.59 h45
  text "L1-TOP - L6-BOT" at -10294.2,-47.59 h45
  text "Pad" at -9400.36,-47.59 h45
  text "+/-3.00mil" at -8956.37,-47.59 h45
  text "2" at -12181.87,-160.09 h45
  text "35.43mil (0.900mm)" at -11686.01,-160.09 h45
  text "PTH" at -10675.2,-160.09 h45
  text "L1-TOP - L6-BOT" at -10294.2,-160.09 h45
  text "Pad" at -9400.36,-160.09 h45
  text "+/-3.00mil" at -8956.37,-160.09 h45
  text "16" at -12181.87,-272.59 h45
  text "40.16mil (1.020mm)" at -11686.01,-272.59 h45
  text "NPTH" at -10675.2,-272.59 h45
  text "L1-TOP - L6-BOT" at -10294.2,-272.59 h45
  text "Pad" at -9400.36,-272.59 h45
  text "+/-3.00mil" at -8956.37,-272.59 h45
  text "4" at -12181.87,-385.09 h45
  text "41.34mil (1.050mm)" at -11686.01,-385.09 h45
  text "NPTH" at -10675.2,-385.09 h45
  text "L1-TOP - L6-BOT" at -10294.2,-385.09 h45
  text "Pad" at -9400.36,-385.09 h45
  text "+/-3.00mil" at -8956.37,-385.09 h45
  text "44" at -12181.87,-497.59 h45
  text "41.34mil (1.050mm)" at -11686.01,-497.59 h45
  text "PTH" at -10675.2,-497.59 h45
  text "L1-TOP - L6-BOT" at -10294.2,-497.59 h45
  text "Pad" at -9400.36,-497.59 h45
  text "+/-3.00mil" at -8956.37,-497.59 h45
  text "3" at -12181.87,-610.09 h45
  text "59.06mil (1.500mm)" at -11686.01,-610.09 h45
  text "PTH" at -10675.2,-610.09 h45
  text "L1-TOP - L6-BOT" at -10294.2,-610.09 h45
  text "Pad" at -9400.36,-610.09 h45
  text "+/-3.00mil" at -8956.37,-610.09 h45
  text "8" at -12181.87,-722.59 h45
  text "61.02mil (1.550mm)" at -11686.01,-722.59 h45
  text "NPTH" at -10675.2,-722.59 h45
  text "L1-TOP - L6-BOT" at -10294.2,-722.59 h45
  text "Pad" at -9400.36,-722.59 h45
  text "+/-3.00mil" at -8956.37,-722.59 h45
  text "10" at -12181.87,-835.09 h45
  text "65.00mil (1.651mm)" at -11686.01,-835.09 h45
  text "PTH" at -10675.2,-835.09 h45
  text "L1-TOP - L6-BOT" at -10294.2,-835.09 h45
  text "Pad" at -9400.36,-835.09 h45
  text "+/-3.00mil" at -8956.37,-835.09 h45
  text "6" at -12181.87,-947.59 h45
  text "70.87mil (1.800mm)" at -11686.01,-947.59 h45
  text "PTH" at -10675.2,-947.59 h45
  text "L1-TOP - L6-BOT" at -10294.2,-947.59 h45
  text "Pad" at -9400.36,-947.59 h45
  text "+/-3.00mil" at -8956.37,-947.59 h45
  text "A" at -12585.04,-955.58 h50
  text "2" at -12181.87,-1060.09 h45
  text "118.11mil (3.000mm)" at -11686.01,-1060.09 h45
  text "NPTH" at -10675.2,-1060.09 h45
  text "L1-TOP - L6-BOT" at -10294.2,-1060.09 h45
  text "Pad" at -9400.36,-1060.09 h45
  text "+/-3.00mil" at -8956.37,-1060.09 h45
  text "14" at -12181.87,-1172.59 h45
  text "125.98mil (3.200mm)" at -11686.01,-1172.59 h45
  text "PTH" at -10675.2,-1172.59 h45
  text "L1-TOP - L6-BOT" at -10294.2,-1172.59 h45
  text "Pad" at -9400.36,-1172.59 h45
  text "+/-3.00mil" at -8956.37,-1172.59 h45
  text "4" at -12181.87,-1285.09 h45
  text "137.79mil (3.500mm)" at -11686.01,-1285.09 h45
  text "NPTH" at -10675.2,-1285.09 h45
  text "L1-TOP - L6-BOT" at -10294.2,-1285.09 h45
  text "Pad" at -9400.36,-1285.09 h45
  text "+/-3.00mil" at -8956.37,-1285.09 h45
  text "E" at -12585.04,-1293.08 h50
  text "4" at -12181.87,-1397.59 h45
  text "250.00mil (6.350mm)" at -11686.01,-1397.59 h45
  text "NPTH" at -10675.2,-1397.59 h45
  text "L1-TOP - L6-BOT" at -10294.2,-1397.59 h45
  text "Pad" at -9400.36,-1397.59 h45
  text "+/-3.00mil" at -8956.37,-1397.59 h45
  text "Press-fit" at -8143.5,-1397.59 h45
  text "2096 Total" at -12181.87,-1510.09 h45
  text "Slot definitions :" at -12562.88,-1619.82 h45
  text "Routed Path Length" at -11786.96,-1619.82 h45
  text "= Calculated from tool start centre position to tool end centre position." at -10958.56,-1619.82 h45
  text "Hole Length" at -11786.96,-1695.8 h45
  text "= Routed Path Length + Tool Size = Slot length as defined in the PCB layout" at -11265.96,-1695.8 h45
Doc-Assy-Top:
  lines w5.29: -6879.65,783.42 -6668.12,783.42 ; -6879.65,3030.86 -6668.12,3030.86 ; -6879.65,5278.31 -6668.12,5278.31 ; -4182.72,-1252.49 -4182.72,-1040.97 ; -4182.72,7102.7 -4182.72,7314.22 ; -1274.26,-1252.49 -1274.26,-1040.97 ; -1274.26,7102.7 -1274.26,7314.22 ; -428.17,-1252.49 4331.12,-1252.49 ; 950.62,-1040.68 950.62,-286.85 4118.72,-286.85 ; 950.62,-786.29 4118.72,-786.29 ; 1428.71,-1040.68 1428.71,-786.29 ; 1634.19,-1252.49 1634.19,-1040.97 ; 1634.19,7102.7 1634.19,7314.22 ; 2170.46,-1040.68 2170.46,-786.29 ; 2318.77,-785.97 2318.77,-286.85 ; 3266.96,-1040.68 3266.96,-786.29 ; 4119.59,783.42 4331.12,783.42 ; 4119.59,3030.86 4331.12,3030.86 ; 4119.59,5278.31 4331.12,5278.31 ; 4331.12,-1252.49 -6879.65,-1252.49 -6879.65,7314.22 4331.12,7314.22 4331.12,-1252.49 ; -6668.12,-1040.97 4119.59,-1040.97 4119.59,7102.7 -6668.12,7102.7 -6668.12,-1040.97
  text "1" at -5661.97,7174.77 h74.03
  text "2" at -2752.82,7174.77 h74.03
  text "3" at 150.35,7174.77 h74.03
  text "4" at 3059.87,7174.77 h74.03
  text "A" at -6803.66,6306.31 h74.03
  text "A" at 4202.25,6306.31 h74.03
  text "B" at -6803.66,4058.87 h74.03
  text "B" at 4202.25,4058.87 h74.03
  text "C" at -6803.66,1811.43 h74.03
  text "C" at 4202.25,1811.43 h74.03
  text "TITLE:" at 1032.72,-370.09 h47.57
  text "Opal Kelly" at 2402.01,-403.38 h74
  text "D" at -6803.66,-430.72 h74.03
  text "D" at 4202.25,-430.72 h74.03
  text "13500 SW 72nd Ave Suite 100" at 2402.01,-528.24 h74
  text "Portland, OR 97223" at 2402.01,-632.29 h74
  text "'.Part_Number' / Assembly Drawing" at 1066.94,-634.07 h74
  text "www.opalkelly.com" at 2402.01,-736.34 h74
  text "(Top)" at 1066.94,-754.59 h74
  text "REV:" at 1009.46,-856.78 h47.57
  text "SIZE:" at 1493.21,-856.78 h47.57
  text "ENGINEER:" at 2234.96,-856.78 h47.57
  text "DATE:" at 3331.46,-856.78 h47.57
  text "'.PCB_Revision'XX" at 1073.96,-985.78 h74
  text "ANSI A" at 1557.71,-985.78 h74
  text "RCA" at 2299.46,-985.78 h74
  text ".PRINT_DATE" at 3395.96,-985.78 h74
  text "1" at -5661.97,-1187.08 h74.03
  text "2" at -2752.82,-1187.08 h74.03
  text "3" at 150.35,-1187.08 h74.03
  text "4" at 3059.87,-1187.08 h74.03
Doc-Assy-Bot:
  lines w5.29: -6878.46,783.92 -6666.92,783.92 ; -6878.46,3031.54 -6666.92,3031.54 ; -6878.46,5279.15 -6666.92,5279.15 ; -6666.05,-785.91 -3497.7,-785.91 ; -6666.05,-286.44 -3497.7,-286.44 -3497.7,-1040.33 ; -5814.23,-1040.33 -5814.23,-785.91 ; -4865.96,-785.6 -4865.96,-286.44 ; -4717.64,-1040.33 -4717.64,-785.91 ; -4181.32,-1252.16 -4181.32,-1040.62 ; -4181.32,7103.69 -4181.32,7315.23 ; -3975.83,-1040.33 -3975.83,-785.91 ; -2118.81,-1252.16 -6878.46,-1252.16 ; -1272.64,-1252.16 -1272.64,-1040.62 ; -1272.64,7103.69 -1272.64,7315.23 ; 1636.04,-1252.16 1636.04,-1040.62 ; 1636.04,7103.69 1636.04,7315.23 ; 4121.63,783.92 4333.17,783.92 ; 4121.63,3031.54 4333.17,3031.54 ; 4121.63,5279.15 4333.17,5279.15 ; -6878.46,-1252.16 -6878.46,7315.23 4333.17,7315.23 4333.17,-1252.16 -6878.46,-1252.16 ; -6666.92,-1040.62 -6666.92,7103.69 4121.63,7103.69 4121.63,-1040.62 -6666.92,-1040.62
  text "4" at -5607.12,7175.77 h74.04
  text "3" at -2697.37,7175.77 h74.04
  text "2" at 206.02,7175.77 h74.04
  text "1" at 3115.4,7175.77 h74.04
  text "A" at -6749.58,6307.24 h74.04
  text "A" at 4257.18,6307.24 h74.04
  text "B" at -6749.58,4059.62 h74.04
  text "B" at 4257.18,4059.62 h74.04
  text "C" at -6749.58,1812.01 h74.04
  text "C" at 4257.18,1812.01 h74.04
  text "TITLE:" at -3579.8,-369.68 h47.58
  text "Opal Kelly" at -4949.2,-402.98 h74.01
  text "D" at -6749.58,-430.32 h74.04
  text "D" at 4257.18,-430.32 h74.04
  text "13500 SW 72nd Ave Suite 100" at -4949.2,-527.85 h74.01
  text "Portland, OR 97223" at -4949.2,-631.91 h74.01
  text "'.Part_Number' / Assembly Drawing" at -3614.03,-633.69 h74.01
  text "www.opalkelly.com" at -4949.2,-735.97 h74.01
  text "(Bottom)" at -3614.03,-754.21 h74.01
  text "DATE:" at -5878.73,-856.41 h47.58
  text "ENGINEER:" at -4782.14,-856.41 h47.58
  text "SIZE:" at -4040.34,-856.41 h47.58
  text "REV:" at -3556.55,-856.41 h47.58
  text ".PRINT_DATE" at -5943.24,-985.42 h74.01
  text "RCA" at -4846.65,-985.42 h74.01
  text "ANSI A" at -4104.84,-985.42 h74.01
  text "'.PCB_Revision'XX" at -3621.05,-985.42 h74.01
  text "4" at -5607.12,-1186.74 h74.04
  text "3" at -2697.37,-1186.74 h74.04
  text "2" at 206.02,-1186.74 h74.04
  text "1" at 3115.4,-1186.74 h74.04
Doc-Fab:
  lines w5: -1585.28,-3180.41 -1585.28,-2124.27 2953.91,-2124.27 ; -1585.28,-2314.27 174.72,-2314.27 ; -1585.28,-2204.27 174.72,-2204.27 ; -1165.28,-3180.41 -1165.28,-2124.27 ; 174.72,-3180.41 174.72,-2124.27 ; 174.72,-2984.27 2954.72,-2984.27 ; 174.72,-2544.27 2953.91,-2544.27 ; 734.72,-3180.41 734.72,-2984.27 ; 1414.72,-2984.27 1414.72,-2544.27 ; 2064.72,-3180.41 2064.72,-2984.27
  lines w5.49: -13309.11,-792.09 -13089.33,-792.09 ; -13309.11,1817.85 -13089.33,1817.85 ; -13309.11,4427.79 -13089.33,4427.79 ; -10561.81,-3402.03 -10561.81,-3182.24 ; -10561.81,6817.95 -10561.81,7037.73 ; -7814.5,-3402.03 -7814.5,-3182.24 ; -7814.5,6817.95 -7814.5,7037.73 ; -5067.2,-3402.03 -5067.2,-3182.24 ; -5067.2,6817.95 -5067.2,7037.73 ; -2319.89,-3402.03 -2319.89,-3182.24 ; -2319.89,6817.95 -2319.89,7037.73 ; 427.41,-3402.03 427.41,-3182.24 ; 427.41,6817.95 427.41,7037.73 ; 2954.93,-792.09 3174.72,-792.09 ; 2954.93,1817.85 3174.72,1817.85 ; 2954.93,4427.79 3174.72,4427.79 ; -13309.11,-3402.03 3174.72,-3402.03 3174.72,7037.73 -13309.11,7037.73 -13309.11,-3402.03 ; -13089.33,-3182.24 2954.93,-3182.24 2954.93,6817.95 -13089.33,6817.95 -13089.33,-3182.24
  text "1" at -11955.97,6894.87 h76.92
  text "2" at -9213.43,6894.87 h76.92
  text "3" at -6477.84,6894.87 h76.92
  text "4" at -3723.21,6894.87 h76.92
  text "5" at -977.01,6894.87 h76.92
  text "6" at 1775.79,6894.87 h76.92
  text "A" at -13226.69,5638.8 h76.92
  text "A" at 3037.35,5638.8 h76.92
  text "B" at -13226.69,3023.37 h76.92
  text "B" at 3037.35,3023.37 h76.92
  text "C" at -13226.69,413.43 h76.92
  text "C" at 3037.35,413.43 h76.92
  text "REVISION:" at -1556.28,-2184.27 h40
  text "DESCRIPTION:" at -1126.28,-2184.27 h40
  text "D" at -13226.69,-2191.01 h76.92
  text "D" at 3037.35,-2191.01 h76.92
  text "PART NUMBER:" at 254.72,-2264.27 h75
  text "AXX" at -1555.28,-2284.27 h50
  text "Initial Release" at -1125.28,-2284.27 h50
  text "'.Part_Number'-PCB-'.PCB_Revision'XX" at 274.72,-2544.27 h130
  text "TITLE:" at 234.72,-2624.27 h40
  text "Opal Kelly" at 1474.72,-2644.27 h60
  text "13500 SW 72nd Ave Suite 100" at 1474.72,-2744.27 h60
  text "Portland, OR 97223" at 1474.72,-2844.27 h60
  text "'.Part_Number' / Fabrication Drawing" at 274.72,-2924.27 h60
  text "www.opalkelly.com" at 1474.72,-2944.27 h60
  text "SIZE:" at 234.72,-3044.27 h40
  text "ENGINEER:" at 794.72,-3044.27 h40
  text "DATE:" at 2114.72,-3044.27 h40
  text "ANSI A" at 274.72,-3144.27 h60
  text "RCA" at 834.72,-3144.27 h60
  text ".PRINT_DATE" at 2154.72,-3144.27 h60
  text "1" at -11955.97,-3325.1 h76.92
  text "2" at -9213.43,-3325.1 h76.92
  text "3" at -6477.84,-3325.1 h76.92
  text "4" at -3723.21,-3325.1 h76.92
  text "5" at -977.01,-3325.1 h76.92
  text "6" at 1775.79,-3325.1 h76.92

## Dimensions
-5708.66,5708.66 to 2559.05,5708.66 on Dimensions
-5708.66,5708.66 to -5708.66,0 on Dimensions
